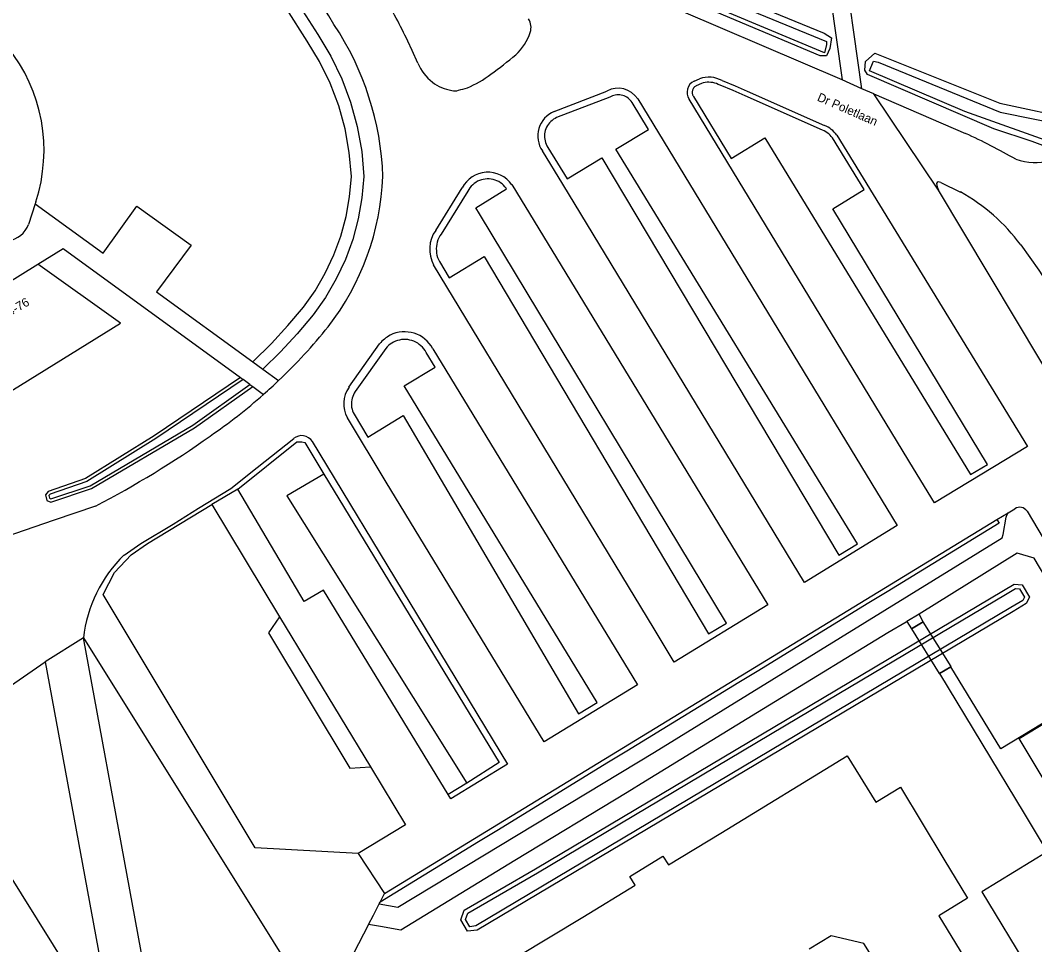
# Model space of a CAD drawing. Extents: x 158132 to 159658, y 385257 to 387209.
# Drawn here: x 158558.9 to 158675.2, y 386762.4 to 386868.4 of the extents above; entities that cross this region are included whole.
import ezdxf

# ---------------------------------------------------------------- set-up
doc = ezdxf.new("R2010")
doc.units = 0
for name, color, linetype in [('IMGEO_Berm_groen', 7, 'Continuous'), ('IMGEO_Dek', 7, 'Continuous'), ('IMGEO_Gemengd_bos', 7, 'Continuous'), ('IMGEO_Groenvoorziening', 7, 'Continuous'), ('IMGEO_Openbare_ruimte_label', 7, 'Continuous'), ('IMGEO_Pand', 7, 'Continuous'), ('IMGEO_Pand_nummerreeks', 7, 'Continuous'), ('IMGEO_Parkeervlak_open', 7, 'Continuous'), ('IMGEO_Rijbaan_lokaal_gesloten', 7, 'Continuous'), ('IMGEO_Rijbaan_lokaal_open', 7, 'Continuous'), ('IMGEO_Voetpad_gesloten', 7, 'Continuous'), ('IMGEO_Voetpad_open', 7, 'Continuous'), ('IMGEO_Waterloop', 7, 'Continuous')]:
    doc.layers.add(name, color=color, linetype=linetype)

msp = doc.modelspace()

# ---------------------------------------------------------------- linework, layer by layer
at = {"layer": 'IMGEO_Berm_groen'}
msp.add_lwpolyline([(158584.11, 386827.41), (158574.21, 386820.73), (158566.33, 386815.83), (158562.05, 386814.36), (158561.74, 386813.95), (158561.9, 386813.3), (158562.37, 386813.13), (158567.02, 386814.67), (158578.84, 386821.64), (158585.52, 386826.38)], dxfattribs=at)
at = {"layer": 'IMGEO_Dek'}
msp.add_lwpolyline([(158662.41, 386799.41), (158661.04, 386798.6), (158664.23, 386793.47), (158664.26, 386793.49), (158665.56, 386794.25), (158665.61, 386794.28)], close=True, dxfattribs=at)
at = {"layer": 'IMGEO_Gemengd_bos'}
msp.add_lwpolyline([(158656.87, 386864.6), (158671.2, 386858.87), (158680.09, 386856.96), (158679.66, 386854.1), (158679.08, 386853.88), (158677.76, 386853.39), (158674.89, 386854.45), (158670.51, 386855.93), (158656.02, 386862.13), (158655.71, 386862.64), (158655.77, 386863.65), (158656.87, 386864.6)], dxfattribs=at)
at = {"layer": 'IMGEO_Groenvoorziening'}
for points in [[(158651.05, 386866.89), (158651.9, 386866.34), (158651.69, 386865.11), (158651.3, 386864.28), (158650.59, 386864.28), (158629.61, 386873.15), (158629.28, 386873.81), (158629.65, 386874.86), (158629.77, 386875.18), (158630.42, 386875.36), (158651.05, 386866.89)], [(158611.25, 386764.05), (158610.15, 386763.93), (158609.37, 386765.23), (158609.77, 386766.36), (158617.93, 386771.08), (158652.46, 386791.61), (158671.6, 386802.98), (158672.85, 386803.73), (158673.76, 386803.64), (158674.59, 386802.25), (158674.22, 386801.5), (158672.71, 386800.6), (158611.25, 386764.05)]]:
    msp.add_lwpolyline(points, dxfattribs=at)
at = {"layer": 'IMGEO_Pand'}
for points in [[(158549.3, 386820.6), (158570.34, 386833.65), (158560.86, 386840.39)], [(158553.66, 386835.92), (158560.86, 386840.39)], [(158577.07, 386740.01), (158576.75, 386739.81), (158566.1, 386797.56)], [(158566.1, 386797.56), (158595.06, 386751.27)], [(158561.73, 386794.82), (158569.83, 386750.88), (158549.96, 386782.63)], [(158557.72, 386792.05), (158561.73, 386794.82)], [(158673.39, 386786.05), (158680, 386790.03), (158691.55, 386770.8), (158688.24, 386768.81), (158690.71, 386764.69), (158687.4, 386762.71), (158673.39, 386786.05)], [(158608.37, 386756.55), (158623.38, 386765.55), (158629.36, 386769.21), (158628.76, 386770.22), (158632.56, 386772.54), (158633.18, 386771.55), (158639.18, 386775.19), (158653.7, 386784.05), (158656.95, 386778.72)], [(158656.95, 386778.72), (158659.8, 386780.45), (158664.76, 386772.2), (158667.49, 386767.72), (158664.21, 386765.71), (158672.78, 386751.6)], [(158657.18, 386759.99), (158655.61, 386762.55), (158651.85, 386763.43), (158649.32, 386761.88)]]:
    msp.add_lwpolyline(points, dxfattribs=at)
at = {"layer": 'IMGEO_Parkeervlak_open'}
for points in [[(158655.62, 386848.95), (158651.99, 386854.88), (158651.86, 386855.04), (158651.72, 386855.19), (158651.56, 386855.34), (158651.4, 386855.46), (158651.22, 386855.58), (158651.04, 386855.68), (158650.85, 386855.76), (158641.98, 386859.69), (158640.59, 386860.3), (158639.1, 386860.91), (158638.9, 386861.01), (158638.7, 386861.1), (158638.49, 386861.16), (158638.27, 386861.21), (158638.05, 386861.24), (158637.83, 386861.25), (158637.61, 386861.25), (158637.39, 386861.22), (158637.18, 386861.18), (158636.96, 386861.12), (158636.38, 386860.86), (158636.31, 386860.82), (158636.25, 386860.78), (158636.19, 386860.73), (158636.14, 386860.68), (158636.09, 386860.62), (158636.04, 386860.56), (158636.01, 386860.49), (158635.97, 386860.42), (158635.95, 386860.35), (158635.93, 386860.28), (158635.91, 386860.2), (158635.91, 386860.12), (158635.91, 386860.05), (158635.91, 386859.97), (158635.93, 386859.9), (158635.95, 386859.82), (158635.98, 386859.75), (158636.01, 386859.68), (158636.05, 386859.62), (158640.36, 386852.51), (158644.24, 386854.87), (158667.84, 386816.28), (158669.78, 386817.45), (158652.02, 386846.74), (158655.62, 386848.95)], [(158654.87, 386808.35), (158627.17, 386853.57), (158630.91, 386855.84), (158629.03, 386858.93), (158628.93, 386859.07), (158628.81, 386859.2), (158628.69, 386859.32), (158628.55, 386859.43), (158628.41, 386859.53), (158628.26, 386859.61), (158628.11, 386859.68), (158627.94, 386859.73), (158627.77, 386859.77), (158627.61, 386859.8), (158627.43, 386859.81), (158627.26, 386859.81), (158627.09, 386859.79), (158626.92, 386859.75), (158626.76, 386859.7), (158626.6, 386859.64), (158626.45, 386859.56), (158620.36, 386857.2), (158620.18, 386857.11), (158620, 386857.01), (158619.84, 386856.89), (158619.69, 386856.76), (158619.55, 386856.61), (158619.42, 386856.45), (158619.3, 386856.29), (158619.21, 386856.11), (158619.13, 386855.92), (158619.06, 386855.73), (158619.01, 386855.53), (158618.98, 386855.33), (158618.97, 386855.13), (158618.98, 386854.93), (158619, 386854.73), (158619.04, 386854.53), (158619.1, 386854.34), (158619.17, 386854.15), (158619.26, 386853.97), (158619.37, 386853.79), (158621.58, 386850.17), (158625.55, 386852.58), (158652.74, 386807.04), (158654.87, 386808.35)], [(158608.05, 386838.84), (158612.05, 386841.27), (158637.79, 386798.01), (158639.85, 386799.25), (158611.51, 386846.18), (158611.09, 386846.87), (158614.63, 386849.02), (158614.58, 386849.1), (158614.44, 386849.28), (158614.28, 386849.45), (158614.11, 386849.6), (158613.93, 386849.74), (158613.73, 386849.86), (158613.52, 386849.96), (158613.31, 386850.04), (158613.09, 386850.11), (158612.87, 386850.15), (158612.64, 386850.17), (158612.41, 386850.18), (158612.18, 386850.16), (158611.95, 386850.12), (158611.73, 386850.07), (158611.51, 386849.99), (158611.3, 386849.9), (158611.11, 386849.78), (158610.92, 386849.65), (158610.74, 386849.5), (158610.58, 386849.34), (158610.43, 386849.16), (158610.3, 386848.98), (158610.19, 386848.78), (158607.13, 386843.86), (158606.99, 386843.64), (158606.86, 386843.42), (158606.76, 386843.18), (158606.68, 386842.94), (158606.62, 386842.69), (158606.58, 386842.44), (158606.56, 386842.18), (158606.57, 386841.92), (158606.6, 386841.67), (158606.64, 386841.42), (158606.71, 386841.17), (158606.81, 386840.93), (158606.92, 386840.7), (158608.05, 386838.84)], [(158625, 386790.16), (158602.9, 386826.46), (158606.42, 386828.61), (158605.4, 386830.28), (158605.28, 386830.49), (158605.14, 386830.68), (158604.98, 386830.87), (158604.81, 386831.04), (158604.62, 386831.2), (158604.43, 386831.33), (158604.22, 386831.45), (158604, 386831.56), (158603.77, 386831.64), (158603.54, 386831.7), (158603.3, 386831.75), (158603.06, 386831.77), (158602.81, 386831.77), (158602.57, 386831.75), (158602.33, 386831.71), (158602.1, 386831.65), (158601.87, 386831.57), (158601.65, 386831.47), (158601.45, 386831.36), (158601.26, 386831.23), (158601.08, 386831.09), (158600.92, 386830.92), (158600.77, 386830.75), (158597.27, 386825.79), (158597.16, 386825.61), (158597.06, 386825.43), (158596.98, 386825.24), (158596.92, 386825.04), (158596.87, 386824.84), (158596.84, 386824.63), (158596.83, 386824.42), (158596.83, 386824.21), (158596.86, 386824), (158596.9, 386823.8), (158596.96, 386823.6), (158597.03, 386823.4), (158597.13, 386823.22), (158598.72, 386820.59), (158602.77, 386823.04), (158622.88, 386788.87), (158625, 386790.16)], [(158593.68, 386816.35), (158589.44, 386813.85), (158610.05, 386780.91)], [(158588.57, 386799.98), (158587.34, 386798.13), (158596.66, 386782.63), (158599.02, 386782.78)]]:
    msp.add_lwpolyline(points, dxfattribs=at)
at = {"layer": 'IMGEO_Rijbaan_lokaal_gesloten'}
for points in [[(158653.1, 386861.53), (158630.22, 386871.36), (158627.88, 386872.37)], [(158604.45, 386863.44), (158603.8, 386864.88), (158603.29, 386865.98)], [(158636.13, 386861.39), (158636.75, 386861.66)], [(158655.38, 386860.52), (158653.1, 386861.53)], [(158639.36, 386861.44), (158640.82, 386860.84), (158642.21, 386860.22), (158651.07, 386856.3)], [(158656.73, 386859.94), (158655.38, 386860.52)], [(158620.08, 386857.9), (158626.12, 386860.25)], [(158629.67, 386859.34), (158659.42, 386810.44)], [(158663.69, 386813.05), (158661.27, 386816.98), (158635.55, 386859.3)], [(158664.17, 386848.88), (158656.73, 386859.94)], [(158656.73, 386859.94), (158667.25, 386855.4)], [(158652.48, 386855.2), (158674.35, 386819.51), (158663.69, 386813.05)], [(158659.42, 386810.44), (158648.79, 386803.92), (158621.06, 386849.56), (158618.73, 386853.38)], [(158606.5, 386844.28), (158609.53, 386849.15)], [(158615.21, 386849.52), (158644.57, 386801.34)], [(158678.81, 386824.43), (158664.17, 386848.88)], [(158664.41, 386849.76), (158666.67, 386848.67)], [(158560.64, 386847.54), (158560.57, 386847.32)], [(158560.57, 386847.32), (158559.81, 386844.96)], [(158673.58, 386842.6), (158675.65, 386839.71), (158677.11, 386837.46), (158681.3, 386830.5)], [(158644.57, 386801.34), (158633.83, 386794.79), (158631.54, 386798.59), (158606.26, 386840.32)], [(158596.55, 386826.3), (158600.06, 386831.28)], [(158606.17, 386830.71), (158629.65, 386792.2), (158618.92, 386785.65)], [(158618.92, 386785.65), (158600.82, 386815.43), (158596.37, 386822.78)], [(158570.76, 386807.06), (158572.68, 386808.39), (158576.41, 386810.6), (158579.29, 386812.42), (158582.99, 386814.68), (158586.02, 386817.09), (158590.21, 386820.42)], [(158592.35, 386820.08), (158614.74, 386783.09), (158608.24, 386779.1), (158607.93, 386779.62)], [(158583.8, 386814.63), (158580.83, 386812.85)], [(158607.93, 386779.62), (158593.62, 386803.05), (158591.41, 386801.74), (158583.8, 386814.63)], [(158567.49, 386812.68), (158562.73, 386811.07), (158547.09, 386805.66)], [(158580.83, 386812.85), (158588.57, 386799.98)], [(158670.85, 386811.12), (158672.14, 386811.91)], [(158672.14, 386811.91), (158672.9, 386812.37)], [(158674.32, 386812.09), (158676.14, 386809), (158689.49, 386787.04), (158690.28, 386785.75), (158703.28, 386763.8), (158704.17, 386764.35)], [(158600.64, 386768.25), (158612.34, 386775.4), (158670.85, 386811.12)], [(158588.57, 386799.98), (158599.02, 386782.78)], [(158566.1, 386797.56), (158561.73, 386794.82)], [(158599.02, 386782.78), (158603.04, 386776.13), (158597.62, 386772.83)], [(158597.62, 386772.83), (158600.64, 386768.25)]]:
    msp.add_lwpolyline(points, dxfattribs=at)
for centre, radius, start, end in [((158546.29, 386839.62), 56.17, 30.2156, 48.8784), ((158554.48, 386843.09), 53.91, 25.1163, 31.4145), ((158615.64, 386867.55), 1.79, 341.2257, 32.5098), ((158566.71, 386849.21), 33.76, 2.0941, 33.5954), ((158612.03, 386868.56), 5.53, 311.3963, 343.3639), ((158542.62, 386853.44), 18.96, 341.8913, 38.6991), ((158581.87, 386904.81), 52.69, 305.9673, 309.9342), ((158609.52, 386865.59), 5.5, 202.9365, 231.9112), ((158605.15, 386872.38), 12.77, 292.9718, 306.899), ((158637.8, 386858.61), 3.23, 61.1769, 108.9937), ((158608.97, 386864.9), 4.62, 231.9723, 262.2291), ((158608.69, 386861.68), 1.41, 256.0401, 287.4267), ((158592.2, 386923.62), 65.5, 284.962, 285.8895), ((158627.4, 386857.86), 2.71, 33.0764, 118.0838), ((158636.77, 386860.09), 1.45, 116.0276, 212.9242), ((158621.26, 386855.09), 3.05, 112.8892, 213.9941), ((158649.91, 386853.38), 3.15, 35.3147, 68.3061), ((158638.75, 386793.04), 68.56, 60.009, 65.4414), ((158675.25, 386859.02), 6.96, 251.4012, 316.7563), ((158570.53, 386851.59), 29.93, 322.1674, 357.8055), ((158612.48, 386847.6), 3.34, 34.9999, 152.3246), ((158664.17, 386849.63), 0.235, 104.4698, 177.4419), ((158663.8, 386848.38), 1.51, 66.3901, 78.1489), ((158665.71, 386849.78), 1.78, 184.4601, 210.1614), ((158656.34, 386829.96), 21.38, 36.2486, 61.1007), ((158557.01, 386846.07), 3.02, 278.4411, 338.3796), ((158609.53, 386842.11), 3.73, 144.4577, 208.716), ((158544.58, 386873.26), 63.73, 313.5367, 321.0885), ((158602.92, 386828.96), 3.69, 28.3894, 116.7685), ((158602.86, 386829.08), 3.55, 116.8385, 141.8972), ((158545.11, 386872.69), 62.95, 311.4233, 313.5525), ((158544.67, 386873.12), 63.57, 304.451, 311.4618), ((158599.27, 386824.39), 3.32, 144.8477, 209.0738), ((158591.13, 386819.29), 1.46, 32.9568, 129.2103), ((158516.37, 386911.22), 111.01, 297.4181, 305.3687), ((158673.47, 386811.51), 1.03, 34.3302, 123.2366), ((158581.83, 386795.74), 15.84, 134.381, 173.4281)]:
    msp.add_arc(centre, radius, start, end, dxfattribs=at)
at = {"layer": 'IMGEO_Rijbaan_lokaal_open'}
for points in [[(158670.85, 386811.12), (158671.1, 386810.71), (158658.25, 386802.85), (158656.17, 386801.58), (158643.35, 386793.73), (158641.26, 386792.45), (158628.43, 386784.59), (158626.33, 386783.31), (158613.49, 386775.46), (158611.4, 386774.17), (158600.14, 386767.28)], [(158600.14, 386767.28), (158600.64, 386768.25)]]:
    msp.add_lwpolyline(points, dxfattribs=at)
at = {"layer": 'IMGEO_Voetpad_gesloten'}
for points in [[(158638.49, 386916.84), (158640.3, 386917.93), (158646.58, 386907.68), (158653.1, 386861.53)], [(158655.38, 386860.52), (158648.61, 386908.46)]]:
    msp.add_lwpolyline(points, dxfattribs=at)
at = {"layer": 'IMGEO_Voetpad_open'}
for points in [[(158560.57, 386847.32), (158568.36, 386841.66), (158572.21, 386847.05), (158578.45, 386842.59), (158574.49, 386837.22), (158585.51, 386829.22)], [(158560.86, 386840.39), (158563.76, 386842.19), (158584.11, 386827.41)], [(158585.51, 386829.22), (158586.68, 386828.37)], [(158586.68, 386828.37), (158588.48, 386827.06)], [(158584.11, 386827.41), (158584.42, 386827.18)], [(158585.2, 386826.61), (158584.42, 386827.18)], [(158585.2, 386826.61), (158585.52, 386826.38)], [(158585.52, 386826.38), (158586.76, 386825.48)], [(158583.8, 386814.63), (158590.58, 386820.04), (158591.15, 386820.04), (158591.5, 386819.95), (158593.68, 386816.35)], [(158593.68, 386816.35), (158613.78, 386783.29), (158610.05, 386780.91)], [(158597.62, 386772.83), (158585.81, 386773.51), (158568.38, 386802.55), (158569.65, 386805.05), (158571.57, 386807.1), (158573.43, 386808.4), (158580.83, 386812.85)], [(158600.03, 386767.08), (158602.16, 386766.71), (158631.58, 386784.47), (158671.46, 386809.03), (158671.57, 386809.41), (158671.93, 386811.41), (158672.03, 386811.72), (158672.14, 386811.91)], [(158699.63, 386765.83), (158687.88, 386785.52), (158683.77, 386792.31), (158682.34, 386794.67), (158679.27, 386799.74), (158675.13, 386806.7), (158673.19, 386807.26), (158661.93, 386800.29)], [(158661.93, 386800.29), (158660.54, 386799.43)], [(158660.54, 386799.43), (158661.04, 386798.6), (158662.41, 386799.41), (158661.93, 386800.29)], [(158660.54, 386799.43), (158660.44, 386799.37), (158658.36, 386798.14), (158645.46, 386790.27), (158643.39, 386789.02), (158630.55, 386781.13), (158628.47, 386779.83), (158615.58, 386772.04), (158613.51, 386770.8), (158602.49, 386764.07), (158600.17, 386764.48), (158598.81, 386764.72)], [(158662.41, 386799.41), (158661.04, 386798.6), (158664.23, 386793.47), (158664.26, 386793.49), (158665.56, 386794.25), (158665.61, 386794.28), (158662.41, 386799.41)], [(158699.63, 386765.83), (158696.85, 386764.13), (158689.31, 386776.58), (158680.83, 386790.6), (158671.29, 386784.84), (158665.56, 386794.25), (158664.26, 386793.49), (158673.99, 386777.44), (158676.6, 386773.03), (158669.14, 386768.44), (158674.59, 386759.45), (158682.06, 386764.04), (158686.02, 386757.64), (158688.05, 386758.9), (158688.75, 386757.74), (158689.74, 386756.09), (158692.14, 386757.54), (158693.83, 386758.56), (158694.59, 386757.31)], [(158610.05, 386780.91), (158607.93, 386779.62)], [(158600.03, 386767.08), (158600.14, 386767.28)], [(158598.81, 386764.72), (158599.36, 386765.78), (158600.03, 386767.08)], [(158598.81, 386764.72), (158595.4, 386758.15), (158598.25, 386753.23), (158595.06, 386751.27)]]:
    msp.add_lwpolyline(points, dxfattribs=at)
at = {"layer": 'IMGEO_Waterloop'}
for points in [[(158630.15, 386874.64), (158630.33, 386874.56), (158651.3, 386865.91), (158651.3, 386865.58), (158651.1, 386864.61), (158629.77, 386873.58), (158630.15, 386874.64)], [(158585.51, 386829.22), (158587.66, 386831.32), (158589.55, 386833.36), (158591.34, 386835.47), (158592.68, 386837.36), (158593.84, 386839.36), (158594.83, 386841.46), (158595.62, 386843.63), (158596.23, 386845.86), (158596.63, 386848.14), (158596.83, 386850.45), (158596.59, 386853.2), (158596.1, 386855.91), (158595.37, 386858.57), (158594.39, 386861.14), (158593.19, 386863.62), (158591.76, 386865.98), (158589.43, 386869.64)], [(158590.59, 386870.47), (158592.97, 386866.73), (158594.46, 386864.26), (158595.72, 386861.66), (158596.74, 386858.96), (158597.5, 386856.17), (158598.01, 386853.33), (158598.25, 386850.45), (158598.04, 386848.01), (158597.62, 386845.59), (158596.99, 386843.23), (158596.14, 386840.93), (158595.1, 386838.71), (158593.87, 386836.59), (158592.46, 386834.59), (158590.63, 386832.43), (158588.7, 386830.35), (158586.68, 386828.37)], [(158657.22, 386863.55), (158671.23, 386857.84), (158679, 386856.27), (158679, 386854.77), (158678.67, 386854.54), (158678.01, 386854.06), (158667.19, 386857.89), (158656.24, 386862.56), (158656.4, 386862.93), (158656.71, 386863.68), (158657.22, 386863.55)], [(158584.42, 386827.18), (158574.41, 386820.42), (158566.49, 386815.49), (158562.27, 386814.05), (158562.14, 386813.87), (158562.21, 386813.58), (158562.38, 386813.52), (158566.86, 386815.01), (158578.64, 386821.95), (158585.2, 386826.61)], [(158609.92, 386765.29), (158610.18, 386766.02), (158618.18, 386770.65), (158652.72, 386791.18), (158671.85, 386802.55), (158672.97, 386803.21), (158673.46, 386803.17), (158674.02, 386802.23), (158673.84, 386801.86), (158672.45, 386801.03), (158611.09, 386764.54), (158610.42, 386764.46), (158609.92, 386765.29)]]:
    msp.add_lwpolyline(points, dxfattribs=at)

# ---------------------------------------------------------------- texts
at = {"layer": 'IMGEO_Openbare_ruimte_label'}
msp.add_text('Dr Poletlaan', height=1, rotation=336.3575, dxfattribs=at).set_placement((158650.16, 386859.18))
at = {"layer": 'IMGEO_Pand_nummerreeks'}
msp.add_text('74-76', height=1, rotation=29.9485, dxfattribs=at).set_placement((158557.04, 386834.05))

doc.saveas('drawing.dxf')
